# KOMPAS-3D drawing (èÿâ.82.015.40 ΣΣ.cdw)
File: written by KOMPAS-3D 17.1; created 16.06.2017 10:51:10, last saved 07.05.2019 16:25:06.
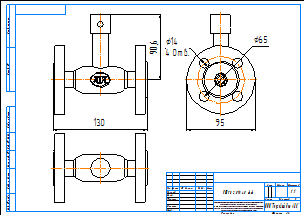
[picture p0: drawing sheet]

Sheet 1: A3, landscape

Title block, sheet 1: name: КШГ.82.015.40 фф; material: Внимание! Данный продукт является объектом авторского права ООО «Торговый Дом АДЛ». / Запрещается изменение, копирование, распространение / (в том числе путем копирования на другие сайты и ресурсы в Интернете) / или любое иное использование информации и объектов без предварительного / согласия правообладателя (ООО «Торговый Дом АДЛ»).; scale: 1:1; sheets: 1; organisation: ООО "Торговый дом АДЛ"; sheet format: A3; stored path: C:\Users\tra\Desktop\2д чертежи\Шаровые краны БИВАЛ\КШ_Бивал_серия_82_85\KOMPAS 2D\КШГ.82.015.40 фф.cdw

Views: Спереди 1, Проекционный вид 2, Проекционный вид 3
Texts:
  Klimkovich
  ADL
Dimensions and other numbers on the sheet: 130; 90,6; 95; 14; 4 Отв.; 65; 1:1; 1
